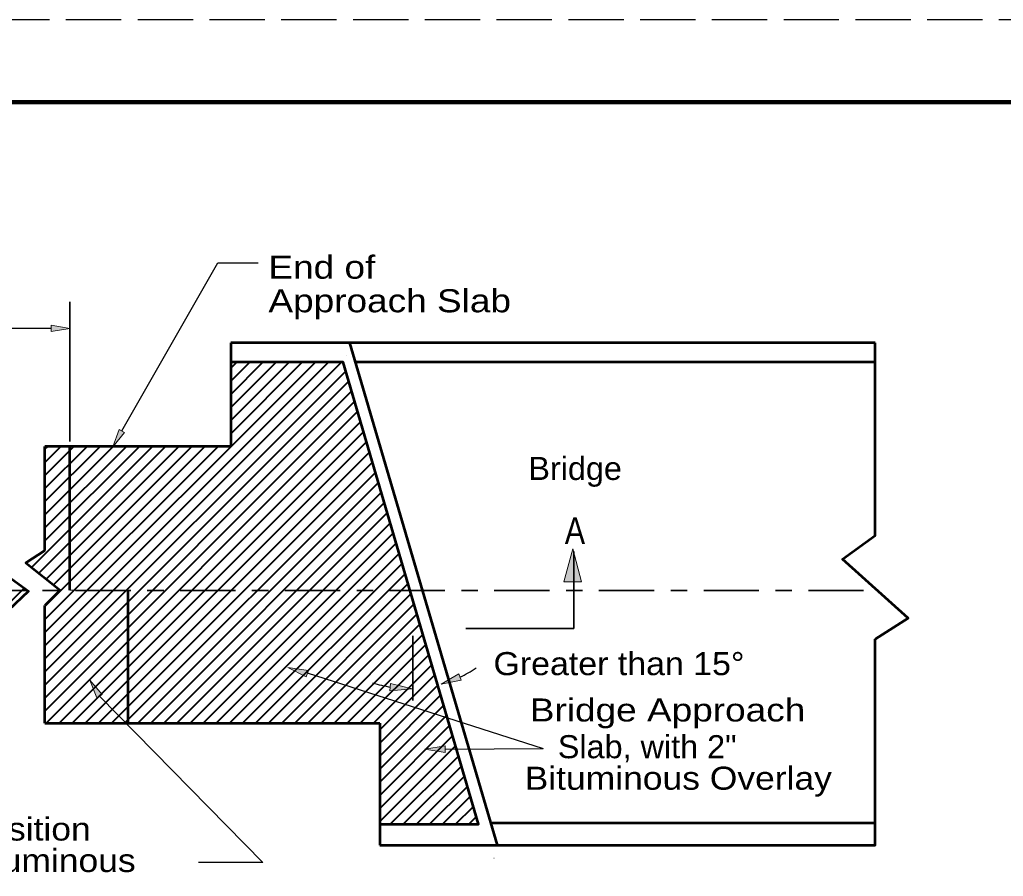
# Model space of a CAD drawing. Extents: x 36.4 to 71.7, y 0.5 to 22.5.
# Drawn here: x 55.29 to 61.26, y 17.27 to 22.48 of the extents above; entities that cross this region are included whole.
import ezdxf

# ---------------------------------------------------------------- set-up
doc = ezdxf.new("R2010")
doc.units = 0
doc.header["$LTSCALE"] = 0.056
doc.linetypes.add('LONG_DASH_SHORT_DASH', pattern=[9.9, 6, -1.2, 1.5, -1.2])
doc.linetypes.add('LONG_DASHED', pattern=[7.5, 6, -1.5])
for name, color, linetype, lineweight in [('1', 7, 'Continuous', 40), ('3', 7, 'Continuous', 13), ('5', 7, 'Continuous', 35), ('6', 7, 'Continuous', 13), ('7', 7, 'LONG_DASH_SHORT_DASH', 35)]:
    doc.layers.add(name, color=color, linetype=linetype, lineweight=lineweight)

msp = doc.modelspace()

# ---------------------------------------------------------------- hatches: boundary and pattern name
at = {"layer": '1'}
for points in [[(55.47983, 20.58408), (55.47983, 20.62158), (55.59233, 20.60283), (55.59233, 20.60283)], [(57.956, 18.50508), (57.97067, 18.46642), (57.84775, 18.44175), (57.84775, 18.44175)], [(57.54058, 18.44692), (57.537, 18.40167), (57.6745, 18.41358), (57.6745, 18.41358)]]:
    msp.add_hatch(color=256, dxfattribs=at).paths.add_polyline_path(points)
at = {"layer": '3'}
for points in [[(55.925, 19.97075), (55.89242, 19.98933), (55.853, 19.88233), (55.853, 19.88233)], [(58.59467, 19.06367), (58.70167, 19.06367), (58.64808, 19.26308), (58.64808, 19.26308)], [(57.02933, 18.48625), (57.04192, 18.5255), (56.91775, 18.5435), (56.91775, 18.5435)], [(55.75692, 18.35958), (55.78883, 18.37925), (55.71392, 18.46525), (55.71392, 18.46525)], [(57.87308, 18.02717), (57.87275, 18.06842), (57.74917, 18.04658), (57.74917, 18.04658)]]:
    msp.add_hatch(color=256, dxfattribs=at).paths.add_polyline_path(points)

# ---------------------------------------------------------------- linework, layer by layer
at = {"layer": '1', "linetype": 'LONG_DASHED', "lineweight": 25}
msp.add_line((71.60142, 22.47742), (36.40142, 22.47742), dxfattribs=at)
at = {"layer": '1', "lineweight": 158}
msp.add_line((71.51808, 21.97742), (39.01808, 21.97742), dxfattribs=at)
at = {"layer": '1', "lineweight": 35}
msp.add_line((55.59233, 19.91658), (55.59233, 20.76483), dxfattribs=at)
at = {"layer": '1', "lineweight": 25}
msp.add_line((55.47983, 20.60283), (52.3805, 20.60283), dxfattribs=at)
at = {"layer": '1', "lineweight": 53}
for p, q in [((60.48592, 20.514), (56.57017, 20.514)), ((58.1915, 17.46367), (57.29408, 20.514)), ((57.32792, 20.399), (60.48592, 20.399)), ((55.44142, 19.25433), (55.44142, 19.88608)), ((55.59233, 19.01367), (55.59233, 19.88608)), ((55.94675, 18.20475), (55.94675, 19.01367)), ((55.44142, 18.20475), (55.44142, 18.92042)), ((55.44142, 18.20475), (57.47592, 18.20475)), ((57.47592, 18.20475), (57.47592, 17.46367)), ((58.15167, 17.59892), (60.48592, 17.59892))]:
    msp.add_line(p, q, dxfattribs=at)
at = {"layer": '1'}
for p, q in [((55.44142, 18.75483), (57.08442, 20.39783)), ((55.44142, 18.67533), (57.16392, 20.39783)), ((55.44142, 18.59575), (57.2435, 20.39783)), ((56.57017, 20.36083), (56.60708, 20.39783)), ((56.57017, 20.28125), (56.68658, 20.39783)), ((56.57017, 20.20167), (56.76617, 20.39783)), ((56.57017, 20.12217), (56.84575, 20.39783)), ((56.57017, 20.04258), (56.92525, 20.39783)), ((56.57017, 19.96308), (57.00483, 20.39783)), ((55.44142, 18.51617), (57.26883, 20.34358)), ((55.44142, 18.43667), (57.28683, 20.282)), ((55.44142, 18.35708), (57.30483, 20.2205)), ((55.44142, 18.2775), (57.32292, 20.15892)), ((55.44817, 18.20475), (57.34092, 20.09742)), ((55.52775, 18.20475), (57.35892, 20.03592)), ((55.60725, 18.20475), (57.37692, 19.97433)), ((55.68683, 18.20475), (57.395, 19.91283)), ((55.35992, 19.15058), (56.09542, 19.88608)), ((55.40425, 19.11542), (56.17492, 19.88608)), ((55.44142, 19.31167), (56.01583, 19.88608)), ((55.44142, 19.39125), (55.93633, 19.88608)), ((55.44142, 19.47075), (55.85675, 19.88608)), ((55.44142, 19.55033), (55.77717, 19.88608)), ((55.44142, 19.62992), (55.69767, 19.88608)), ((55.44142, 19.70942), (55.61808, 19.88608)), ((55.44142, 19.789), (55.5385, 19.88608)), ((55.44142, 19.86858), (55.459, 19.88608)), ((55.44142, 18.91392), (56.41358, 19.88608)), ((55.44142, 18.83433), (56.49308, 19.88608)), ((55.44142, 18.83433), (56.49308, 19.88608)), ((55.44858, 19.08017), (56.25442, 19.88608)), ((55.49292, 19.045), (56.334, 19.88608)), ((55.76642, 18.20475), (57.413, 19.85133)), ((55.84592, 18.20475), (57.431, 19.78983)), ((55.9255, 18.20475), (57.449, 19.72833)), ((56.00508, 18.20475), (57.46708, 19.66675)), ((56.08458, 18.20475), (57.48508, 19.60525)), ((56.16417, 18.20475), (57.50308, 19.54375)), ((56.24375, 18.20475), (57.52117, 19.48217)), ((56.32325, 18.20475), (57.53917, 19.42067)), ((56.40283, 18.20475), (57.55717, 19.35908)), ((56.48242, 18.20475), (57.57517, 19.29758)), ((56.56192, 18.20475), (57.59317, 19.23608)), ((56.64142, 18.20475), (57.61117, 19.1745)), ((56.721, 18.20475), (57.62917, 19.113)), ((54.49358, 18.20475), (55.31467, 19.02575)), ((56.8005, 18.20475), (57.64717, 19.05142)), ((56.88008, 18.20475), (57.66525, 18.98992)), ((56.95967, 18.20475), (57.68325, 18.92842)), ((57.03917, 18.20475), (57.70125, 18.86683)), ((57.11875, 18.20475), (57.71933, 18.80533)), ((57.19825, 18.20475), (57.73733, 18.74383)), ((57.27783, 18.20475), (57.75533, 18.68225)), ((57.35742, 18.20475), (57.77333, 18.62075)), ((57.43692, 18.20475), (57.79142, 18.55917)), ((57.47592, 18.16417), (57.80942, 18.49767)), ((57.47592, 18.08458), (57.82742, 18.43617)), ((57.47592, 18.005), (57.8455, 18.37458)), ((57.47592, 17.9255), (57.8635, 18.31308)), ((57.47592, 17.84592), (57.8815, 18.25158)), ((57.47592, 17.76633), (57.8995, 18.19008)), ((57.47592, 17.68683), (57.91758, 18.12858)), ((57.47592, 17.60733), (57.93558, 18.067)), ((57.53883, 17.59075), (57.95358, 18.0055)), ((57.61842, 17.59075), (57.97158, 17.944)), ((57.69792, 17.59075), (57.98967, 17.88242)), ((57.7775, 17.59075), (58.00767, 17.82092)), ((57.85708, 17.59075), (58.02567, 17.75933)), ((57.93658, 17.59075), (58.04375, 17.69783)), ((58.01617, 17.59075), (58.06175, 17.63633))]:
    msp.add_line(p, q, dxfattribs=at)
at = {"layer": '1', "lineweight": 13}
msp.add_line((55.94675, 19.01367), (55.59233, 19.01367), dxfattribs=at)
for points in [[(55.47983, 20.58408), (55.47983, 20.62158), (55.59233, 20.60283), (55.59233, 20.60283)], [(57.956, 18.50508), (57.97067, 18.46642), (57.84775, 18.44175), (57.84775, 18.44175)], [(57.54058, 18.44692), (57.537, 18.40167), (57.6745, 18.41358), (57.6745, 18.41358)]]:
    msp.add_lwpolyline(points, close=True, dxfattribs=at)
at = {"layer": '1', "lineweight": 53}
for points in [[(56.57017, 20.514), (56.57017, 19.88608), (55.44142, 19.88608)], [(60.48592, 18.71433), (60.68567, 18.84333), (60.28608, 19.20183), (60.48592, 19.34533), (60.48592, 20.514)], [(57.47592, 17.59075), (58.07508, 17.59075), (57.25292, 20.39783), (56.57017, 20.39783)], [(55.2185, 19.27667), (55.06567, 19.20508), (55.3415, 19.00633), (55.2185, 18.88908)], [(55.44142, 19.25433), (55.32467, 19.17858), (55.53308, 19.013), (55.44142, 18.92042)], [(57.47592, 17.46367), (60.48592, 17.46367), (60.48592, 18.71433)]]:
    msp.add_lwpolyline(points, dxfattribs=at)
at = {"layer": '1', "lineweight": 25}
for start, end in [(295.32159, 304.24982), (252.14352, 261.07176)]:
    msp.add_arc((57.65395, 19.13789), 0.72269, start, end, dxfattribs=at)
at = {"layer": '3', "lineweight": 35}
msp.add_line((57.67583, 18.34292), (57.67583, 18.73517), dxfattribs=at)
at = {"layer": '3', "lineweight": 25}
for p in [(57.03533, 18.5115), (57.87217, 18.04633)]:
    msp.add_line(p, (58.46858, 18.05208), dxfattribs=at)
for points in [[(55.90867, 19.98008), (56.49108, 21.00142), (56.73758, 21.00142)], [(55.77292, 18.36942), (56.76517, 17.3595), (56.37442, 17.3595)]]:
    msp.add_lwpolyline(points, dxfattribs=at)
at = {"layer": '3'}
for points in [[(55.925, 19.97075), (55.89242, 19.98933), (55.853, 19.88233), (55.853, 19.88233)], [(58.59467, 19.06367), (58.70167, 19.06367), (58.64808, 19.26308), (58.64808, 19.26308)], [(57.02933, 18.48625), (57.04192, 18.5255), (56.91775, 18.5435), (56.91775, 18.5435)], [(55.75692, 18.35958), (55.78883, 18.37925), (55.71392, 18.46525), (55.71392, 18.46525)], [(57.87308, 18.02717), (57.87275, 18.06842), (57.74917, 18.04658), (57.74917, 18.04658)]]:
    msp.add_lwpolyline(points, close=True, dxfattribs=at)
at = {"layer": '5'}
for p, q in [((58.65367, 19.24742), (58.65367, 18.7795)), ((58.65367, 18.7795), (57.999, 18.7795))]:
    msp.add_line(p, q, dxfattribs=at)
at = {"layer": '6'}
for p, q in [((57.27217, 20.43558), (57.27225, 20.43558)), ((55.59233, 19.86033), (55.59242, 19.86033)), ((57.65392, 18.65675), (57.654, 18.65675)), ((57.65392, 18.2645), (57.654, 18.2645)), ((58.16958, 17.38533), (58.16967, 17.38533))]:
    msp.add_line(p, q, dxfattribs=at)
at = {"layer": '7'}
msp.add_line((50.53942, 19.01133), (60.50117, 19.01133), dxfattribs=at)

# ---------------------------------------------------------------- texts
at = {"layer": '1', "width": 1.1}
msp.add_text('Greater than 15°', height=0.14, dxfattribs=at).set_placement((58.16658, 18.49667))
at = {"layer": '3'}
for s, width, p in [('End of', 1.2, (56.79917, 20.90442)), ('Approach Slab', 1.2, (56.79917, 20.70042)), ('Bridge', 1.05, (58.37842, 19.68208)), ('Bridge Approach', 1.2, (58.38725, 18.21525)), ('Slab, with 2"', 1.05, (58.55742, 17.99225)), ('Bituminous Overlay', 1.15, (58.35575, 17.80092)), ('Concrete Bridge Transition', 1.15, (53.15883, 17.49225)), ('Pavement, with 2" Bituminous', 1.15, (53.13992, 17.301))]:
    msp.add_text(s, height=0.14, dxfattribs=dict(at, width=width)).set_placement(p)
at = {"layer": '5', "width": 0.85}
msp.add_text('A', height=0.162, dxfattribs=at).set_placement((58.59992, 19.294))

doc.saveas('drawing.dxf')
